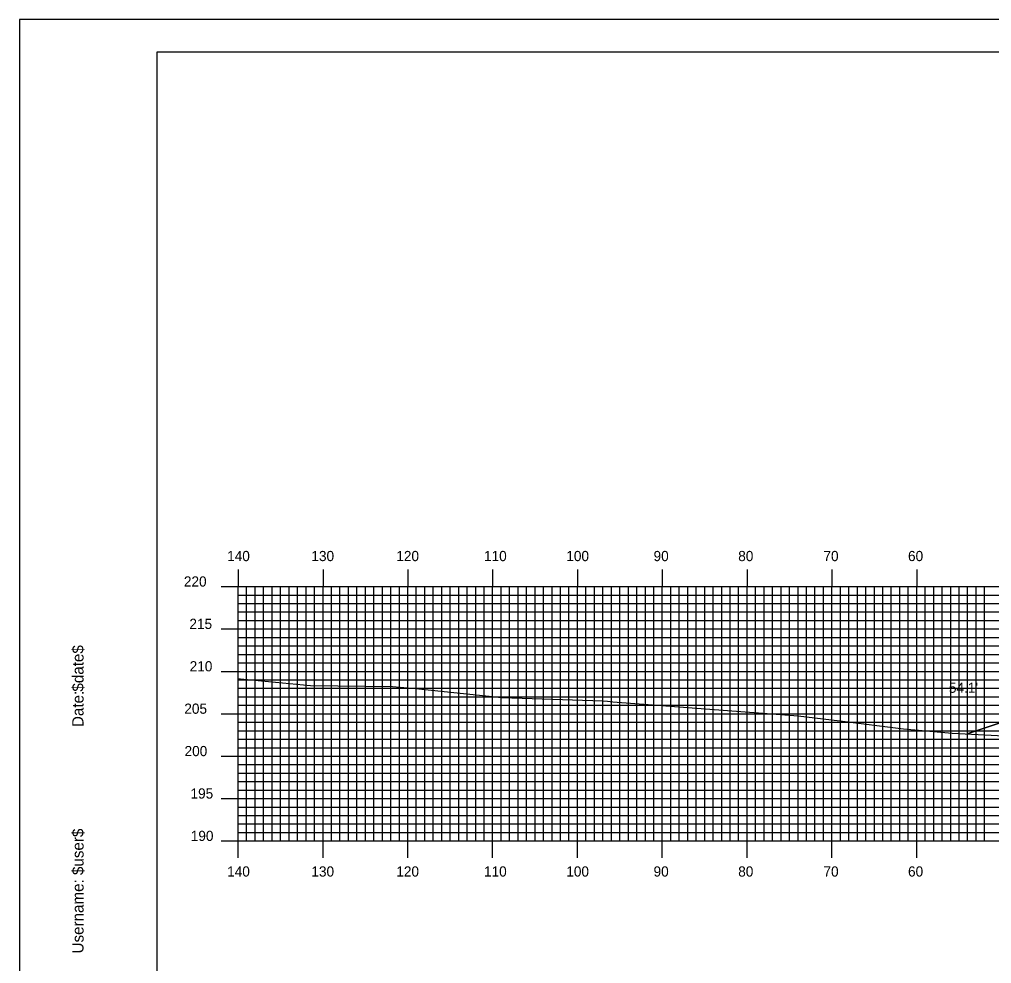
# Model space of a CAD drawing. Extents: x 1805864 to 1806208, y 442591 to 442811.
# Drawn here: x 1805864.4 to 1805979, y 442699.2 to 442810.5 of the extents above; entities that cross this region are included whole.
import ezdxf

# ---------------------------------------------------------------- set-up
doc = ezdxf.new("R2010")
doc.units = 0
for name, color, linetype in [('BORDER', 7, 'Continuous'), ('D_Roadway_Centerline', 7, 'Continuous'), ('D_Roadway_SlopeLines', 7, 'Continuous'), ('D_Text_Standard', 7, 'Continuous'), ('H_V ANNOTATION', 7, 'Continuous'), ('MAJOR', 7, 'Continuous'), ('MINOR', 7, 'Continuous'), ('PLOT BOUNDARY', 7, 'Continuous'), ('S_Roadway_Centerline', 7, 'Continuous')]:
    doc.layers.add(name, color=color, linetype=linetype)

msp = doc.modelspace()

# ---------------------------------------------------------------- linework, layer by layer
at = {"layer": 'BORDER'}
msp.add_lwpolyline([(1805880.62, 442596.67), (1806200.62, 442596.67), (1806200.62, 442806.67), (1805880.62, 442806.67)], close=True, dxfattribs=at)
at = {"layer": 'D_Roadway_Centerline'}
msp.add_lwpolyline([(1805976.16, 442726.29), (1805998.22, 442733.65), (1806000.05, 442734.1), (1806010.22, 442736.65), (1806018.22, 442736.97), (1806030.22, 442737.21), (1806042.22, 442736.97), (1806050.22, 442736.65), (1806060.39, 442734.1), (1806062.22, 442733.65), (1806095.51, 442722.55)], dxfattribs=at)
at = {"layer": 'D_Roadway_SlopeLines'}
msp.add_lwpolyline([(1806010.22, 442736.65), (1805998.22, 442733.65), (1805976.16, 442726.29)], dxfattribs=at)
at = {"layer": 'MAJOR'}
for p, q in [((1805890.22, 442745.67), (1805890.22, 442743.67)), ((1805900.22, 442745.67), (1805900.22, 442743.67)), ((1805910.22, 442745.67), (1805910.22, 442743.67)), ((1805920.22, 442745.67), (1805920.22, 442743.67)), ((1805930.22, 442745.67), (1805930.22, 442743.67)), ((1805940.22, 442745.67), (1805940.22, 442743.67)), ((1805950.22, 442745.67), (1805950.22, 442743.67)), ((1805960.22, 442745.67), (1805960.22, 442743.67)), ((1805970.22, 442745.67), (1805970.22, 442743.67)), ((1805888.22, 442743.67), (1805890.22, 442743.67)), ((1805890.22, 442743.67), (1806170.22, 442743.67)), ((1805890.22, 442713.67), (1805890.22, 442743.67)), ((1805890.22, 442713.67), (1805890.22, 442743.67)), ((1805890.22, 442743.67), (1806170.22, 442743.67)), ((1805900.22, 442713.67), (1805900.22, 442743.67)), ((1805910.22, 442713.67), (1805910.22, 442743.67)), ((1805920.22, 442713.67), (1805920.22, 442743.67)), ((1805930.22, 442713.67), (1805930.22, 442743.67)), ((1805940.22, 442713.67), (1805940.22, 442743.67)), ((1805950.22, 442713.67), (1805950.22, 442743.67)), ((1805960.22, 442713.67), (1805960.22, 442743.67)), ((1805970.22, 442713.67), (1805970.22, 442743.67)), ((1805888.22, 442738.67), (1805890.22, 442738.67)), ((1805890.22, 442738.67), (1806170.22, 442738.67)), ((1805888.22, 442733.67), (1805890.22, 442733.67)), ((1805890.22, 442733.67), (1806170.22, 442733.67)), ((1805888.22, 442728.67), (1805890.22, 442728.67)), ((1805890.22, 442728.67), (1806170.22, 442728.67)), ((1805888.22, 442723.67), (1805890.22, 442723.67)), ((1805890.22, 442723.67), (1806170.22, 442723.67)), ((1805888.22, 442718.67), (1805890.22, 442718.67)), ((1805890.22, 442718.67), (1806170.22, 442718.67)), ((1805888.22, 442713.67), (1805890.22, 442713.67)), ((1805890.22, 442713.67), (1806170.22, 442713.67)), ((1805890.22, 442713.67), (1806170.22, 442713.67)), ((1805890.22, 442711.66), (1805890.22, 442713.67)), ((1805900.22, 442711.66), (1805900.22, 442713.67)), ((1805910.22, 442711.66), (1805910.22, 442713.67)), ((1805920.22, 442711.66), (1805920.22, 442713.67)), ((1805930.22, 442711.66), (1805930.22, 442713.67)), ((1805940.22, 442711.66), (1805940.22, 442713.67)), ((1805950.22, 442711.66), (1805950.22, 442713.67)), ((1805960.22, 442711.66), (1805960.22, 442713.67)), ((1805970.22, 442711.66), (1805970.22, 442713.67))]:
    msp.add_line(p, q, dxfattribs=at)
at = {"layer": 'MINOR'}
for p, q in [((1805891.22, 442713.67), (1805891.22, 442743.67)), ((1805892.22, 442713.67), (1805892.22, 442743.67)), ((1805893.22, 442713.67), (1805893.22, 442743.67)), ((1805894.22, 442713.67), (1805894.22, 442743.67)), ((1805895.22, 442713.67), (1805895.22, 442743.67)), ((1805896.22, 442713.67), (1805896.22, 442743.67)), ((1805897.22, 442713.67), (1805897.22, 442743.67)), ((1805898.22, 442713.67), (1805898.22, 442743.67)), ((1805899.22, 442713.67), (1805899.22, 442743.67)), ((1805901.22, 442713.67), (1805901.22, 442743.67)), ((1805902.22, 442713.67), (1805902.22, 442743.67)), ((1805903.22, 442713.67), (1805903.22, 442743.67)), ((1805904.22, 442713.67), (1805904.22, 442743.67)), ((1805905.22, 442713.67), (1805905.22, 442743.67)), ((1805906.22, 442713.67), (1805906.22, 442743.67)), ((1805907.22, 442713.67), (1805907.22, 442743.67)), ((1805908.22, 442713.67), (1805908.22, 442743.67)), ((1805909.22, 442713.67), (1805909.22, 442743.67)), ((1805911.22, 442713.67), (1805911.22, 442743.67)), ((1805912.22, 442713.67), (1805912.22, 442743.67)), ((1805913.22, 442713.67), (1805913.22, 442743.67)), ((1805914.22, 442713.67), (1805914.22, 442743.67)), ((1805915.22, 442713.67), (1805915.22, 442743.67)), ((1805916.22, 442713.67), (1805916.22, 442743.67)), ((1805917.22, 442713.67), (1805917.22, 442743.67)), ((1805918.22, 442713.67), (1805918.22, 442743.67)), ((1805919.22, 442713.67), (1805919.22, 442743.67)), ((1805921.22, 442713.67), (1805921.22, 442743.67)), ((1805922.22, 442713.67), (1805922.22, 442743.67)), ((1805923.22, 442713.67), (1805923.22, 442743.67)), ((1805924.22, 442713.67), (1805924.22, 442743.67)), ((1805925.22, 442713.67), (1805925.22, 442743.67)), ((1805926.22, 442713.67), (1805926.22, 442743.67)), ((1805927.22, 442713.67), (1805927.22, 442743.67)), ((1805928.22, 442713.67), (1805928.22, 442743.67)), ((1805929.22, 442713.67), (1805929.22, 442743.67)), ((1805931.22, 442713.67), (1805931.22, 442743.67)), ((1805932.22, 442713.67), (1805932.22, 442743.67)), ((1805933.22, 442713.67), (1805933.22, 442743.67)), ((1805934.22, 442713.67), (1805934.22, 442743.67)), ((1805935.22, 442713.67), (1805935.22, 442743.67)), ((1805936.22, 442713.67), (1805936.22, 442743.67)), ((1805937.22, 442713.67), (1805937.22, 442743.67)), ((1805938.22, 442713.67), (1805938.22, 442743.67)), ((1805939.22, 442713.67), (1805939.22, 442743.67)), ((1805941.22, 442713.67), (1805941.22, 442743.67)), ((1805942.22, 442713.67), (1805942.22, 442743.67)), ((1805943.22, 442713.67), (1805943.22, 442743.67)), ((1805944.22, 442713.67), (1805944.22, 442743.67)), ((1805945.22, 442713.67), (1805945.22, 442743.67)), ((1805946.22, 442713.67), (1805946.22, 442743.67)), ((1805947.22, 442713.67), (1805947.22, 442743.67)), ((1805948.22, 442713.67), (1805948.22, 442743.67)), ((1805949.22, 442713.67), (1805949.22, 442743.67)), ((1805951.22, 442713.67), (1805951.22, 442743.67)), ((1805952.22, 442713.67), (1805952.22, 442743.67)), ((1805953.22, 442713.67), (1805953.22, 442743.67)), ((1805954.22, 442713.67), (1805954.22, 442743.67)), ((1805955.22, 442713.67), (1805955.22, 442743.67)), ((1805956.22, 442713.67), (1805956.22, 442743.67)), ((1805957.22, 442713.67), (1805957.22, 442743.67)), ((1805958.22, 442713.67), (1805958.22, 442743.67)), ((1805959.22, 442713.67), (1805959.22, 442743.67)), ((1805961.22, 442713.67), (1805961.22, 442743.67)), ((1805962.22, 442713.67), (1805962.22, 442743.67)), ((1805963.22, 442713.67), (1805963.22, 442743.67)), ((1805964.22, 442713.67), (1805964.22, 442743.67)), ((1805965.22, 442713.67), (1805965.22, 442743.67)), ((1805966.22, 442713.67), (1805966.22, 442743.67)), ((1805967.22, 442713.67), (1805967.22, 442743.67)), ((1805968.22, 442713.67), (1805968.22, 442743.67)), ((1805969.22, 442713.67), (1805969.22, 442743.67)), ((1805971.22, 442713.67), (1805971.22, 442743.67)), ((1805972.22, 442713.67), (1805972.22, 442743.67)), ((1805973.22, 442713.67), (1805973.22, 442743.67)), ((1805974.22, 442713.67), (1805974.22, 442743.67)), ((1805975.22, 442713.67), (1805975.22, 442743.67)), ((1805976.22, 442713.67), (1805976.22, 442743.67)), ((1805977.22, 442713.67), (1805977.22, 442743.67)), ((1805978.22, 442713.67), (1805978.22, 442743.67)), ((1805890.22, 442742.67), (1806170.22, 442742.67)), ((1805890.22, 442742.67), (1805892.22, 442742.67)), ((1805890.22, 442741.67), (1806170.22, 442741.67)), ((1805890.22, 442741.67), (1805892.22, 442741.67)), ((1805890.22, 442740.67), (1806170.22, 442740.67)), ((1805890.22, 442740.67), (1805892.22, 442740.67)), ((1805890.22, 442739.67), (1806170.22, 442739.67)), ((1805890.22, 442739.67), (1805892.22, 442739.67)), ((1805890.22, 442737.67), (1806170.22, 442737.67)), ((1805890.22, 442737.67), (1805892.22, 442737.67)), ((1805890.22, 442736.67), (1806170.22, 442736.67)), ((1805890.22, 442736.67), (1805892.22, 442736.67)), ((1805890.22, 442735.67), (1806170.22, 442735.67)), ((1805890.22, 442735.67), (1805892.22, 442735.67)), ((1805890.22, 442734.67), (1806170.22, 442734.67)), ((1805890.22, 442734.67), (1805892.22, 442734.67)), ((1805890.22, 442732.67), (1806170.22, 442732.67)), ((1805890.22, 442732.67), (1805892.22, 442732.67)), ((1805890.22, 442731.67), (1806170.22, 442731.67)), ((1805890.22, 442731.67), (1805892.22, 442731.67)), ((1805890.22, 442730.67), (1806170.22, 442730.67)), ((1805890.22, 442730.67), (1805892.22, 442730.67)), ((1805890.22, 442729.67), (1806170.22, 442729.67)), ((1805890.22, 442729.67), (1805892.22, 442729.67)), ((1805890.22, 442727.67), (1806170.22, 442727.67)), ((1805890.22, 442727.67), (1805892.22, 442727.67)), ((1805890.22, 442726.67), (1806170.22, 442726.67)), ((1805890.22, 442726.67), (1805892.22, 442726.67)), ((1805890.22, 442725.67), (1806170.22, 442725.67)), ((1805890.22, 442725.67), (1805892.22, 442725.67)), ((1805890.22, 442724.67), (1806170.22, 442724.67)), ((1805890.22, 442724.67), (1805892.22, 442724.67)), ((1805890.22, 442722.67), (1806170.22, 442722.67)), ((1805890.22, 442722.67), (1805892.22, 442722.67)), ((1805890.22, 442721.67), (1806170.22, 442721.67)), ((1805890.22, 442721.67), (1805892.22, 442721.67)), ((1805890.22, 442720.67), (1806170.22, 442720.67)), ((1805890.22, 442720.67), (1805892.22, 442720.67)), ((1805890.22, 442719.67), (1806170.22, 442719.67)), ((1805890.22, 442719.67), (1805892.22, 442719.67)), ((1805890.22, 442717.67), (1806170.22, 442717.67)), ((1805890.22, 442717.67), (1805892.22, 442717.67)), ((1805890.22, 442716.67), (1806170.22, 442716.67)), ((1805890.22, 442716.67), (1805892.22, 442716.67)), ((1805890.22, 442715.67), (1806170.22, 442715.67)), ((1805890.22, 442715.67), (1805892.22, 442715.67)), ((1805890.22, 442714.67), (1806170.22, 442714.67)), ((1805890.22, 442714.67), (1805892.22, 442714.67))]:
    msp.add_line(p, q, dxfattribs=at)
at = {"layer": 'PLOT BOUNDARY'}
msp.add_lwpolyline([(1805864.43, 442590.55), (1806204.43, 442590.55), (1806204.43, 442810.55), (1805864.43, 442810.55)], close=True, dxfattribs=at)
at = {"layer": 'S_Roadway_Centerline'}
msp.add_lwpolyline([(1805890.22, 442732.82), (1805890.5, 442732.8), (1805898.74, 442731.99), (1805908.42, 442731.9), (1805911.12, 442731.63), (1805921.3, 442730.58), (1805933.2, 442730.18), (1805933.75, 442730.14), (1805934.4, 442730.09), (1805956.25, 442728.42), (1805961.15, 442727.82), (1805968.64, 442726.88), (1805974.38, 442726.39), (1805991.94, 442725.48)], dxfattribs=at)

# ---------------------------------------------------------------- texts
at = {"layer": 'BORDER'}
for s, p in [('$date$', (1805871.99, 442731.28)), ('Date:', (1805871.99, 442727.1)), ('$user$', (1805871.99, 442709.65)), ('Username:', (1805871.99, 442700.4))]:
    msp.add_text(s, height=1.339, rotation=90, dxfattribs=at).set_placement(p)
at = {"layer": 'D_Text_Standard'}
msp.add_text("54.1'", height=1.2, dxfattribs=at).set_placement((1805974.01, 442731.14))
at = {"layer": 'H_V ANNOTATION'}
for s, p in [('140', (1805888.92, 442746.67)), ('130', (1805898.85, 442746.67)), ('120', (1805908.86, 442746.67)), ('110', (1805919.2, 442746.67)), ('100', (1805928.9, 442746.67)), ('90', (1805939.19, 442746.67)), ('80', (1805949.17, 442746.67)), ('70', (1805959.22, 442746.67)), ('60', (1805969.19, 442746.67)), ('220', (1805883.82, 442743.67)), ('215', (1805884.47, 442738.67)), ('210', (1805884.5, 442733.67)), ('205', (1805883.87, 442728.67)), ('200', (1805883.9, 442723.67)), ('195', (1805884.6, 442718.67)), ('190', (1805884.63, 442713.67)), ('140', (1805888.92, 442709.47)), ('130', (1805898.85, 442709.47)), ('120', (1805908.86, 442709.47)), ('110', (1805919.2, 442709.47)), ('100', (1805928.9, 442709.47)), ('90', (1805939.19, 442709.47)), ('80', (1805949.17, 442709.47)), ('70', (1805959.22, 442709.47)), ('60', (1805969.19, 442709.47))]:
    msp.add_text(s, height=1.2, dxfattribs=at).set_placement(p)
at = {"layer": 'MAJOR'}
msp.add_text('-', height=0.012, dxfattribs=at).set_placement((1805890.21, 442713.67))

doc.saveas('drawing.dxf')
